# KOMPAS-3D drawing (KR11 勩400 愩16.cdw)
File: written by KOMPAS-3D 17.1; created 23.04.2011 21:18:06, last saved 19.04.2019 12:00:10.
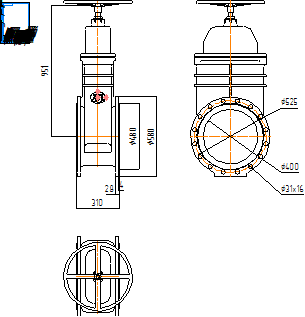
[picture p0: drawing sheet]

Sheet 1: A4, portrait

Title block, sheet 1: name: KR11 Ду400 Ру16; material: Внимание! Данный продукт является объектом авторского права ООО «Торговый Дом АДЛ». / Запрещается изменение, копирование, распространение / (в том числе путем копирования на другие сайты и ресурсы в Интернете) / или любое иное использование информации и объектов без предварительного / согласия правообладателя (ООО «Торговый Дом АДЛ»).; scale: 1:1; sheets: 1; organisation: ООО "Торговый дом АДЛ"; sheet format: A4; stored path: \\adlc.lan\data\АДЛ_ПКД\3D-модели\ADL production\Клиновые задвижки серии KR ГРАНАР\Клиновые задвижки KR11\KOMPAS 2D\KR11 Ду400 Ру16.cdw

Views: Спереди 7, Проекционный вид 8, Проекционный вид 9
Dimensions and other numbers on the sheet: 310; 951; 480; 580; 28; 4; 525; 400; 31; 1:1; 1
